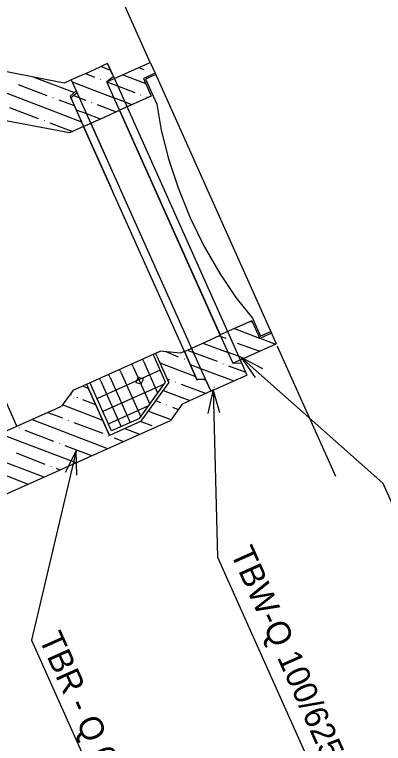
# Model space of a CAD drawing. Extents: x -781656 to -760591, y -1008106 to -975620.
# Drawn here: x -781651.298 to -781650.365, y -1008099.231 to -1008097.386 of the extents above; entities that cross this region are included whole.
import ezdxf

# ---------------------------------------------------------------- set-up
doc = ezdxf.new("R2010")
doc.units = 0
doc.layers.add('Implicitní', color=7, linetype='Continuous')

msp = doc.modelspace()

# ---------------------------------------------------------------- linework, layer by layer
at = {"layer": 'Implicitní'}
for points in [[(-781650.9548, -1008097.5069), (-781651.1925, -1008096.9755)], [(-781651.1726, -1008097.5591), (-781651.8094, -1008097.4335)], [(-781651.0628, -1008097.51), (-781651.0815, -1008097.5183)], [(-781651.0787, -1008097.5171), (-781651.0555, -1008097.5263)], [(-781651.0646, -1008097.5561), (-781650.9548, -1008097.5069)], [(-781651.0628, -1008097.51), (-781651.0503, -1008097.5378), (-781651.0628, -1008097.51)], [(-781650.9548, -1008097.5069), (-781650.9424, -1008097.5345)], [(-781651.4547, -1008097.5323), (-781651.1286, -1008097.6573)], [(-781651.1182, -1008097.5348), (-781651.1546, -1008097.551), (-781651.1421, -1008097.5789)], [(-781651.1189, -1008097.5351), (-781651.0956, -1008097.5442)], [(-781651.1182, -1008097.5348), (-781651.0815, -1008097.5183)], [(-781650.9843, -1008097.5202), (-781650.9712, -1008097.5249)], [(-781650.9424, -1008097.5345), (-781650.972, -1008097.5477), (-781650.9521, -1008097.5923)], [(-781650.9569, -1008097.5304), (-781650.9566, -1008097.531)], [(-781650.9424, -1008097.5345), (-781650.648, -1008098.1927)], [(-781651.2498, -1008097.5443), (-781651.1468, -1008097.583)], [(-781651.1546, -1008097.551), (-781651.1726, -1008097.5591)], [(-781651.1546, -1008097.551), (-781651.1421, -1008097.5789)], [(-781651.0815, -1008097.5493), (-781651.081, -1008097.5504)], [(-781651.048, -1008097.5429), (-781651.0646, -1008097.5561)], [(-781651.0503, -1008097.5378), (-781651.048, -1008097.5429)], [(-781651.048, -1008097.5429), (-781650.7231, -1008098.2692)], [(-781651.0245, -1008097.5381), (-781650.9664, -1008097.5603)], [(-781650.9409, -1008097.5379), (-781650.9668, -1008097.5494), (-781650.9383, -1008097.613)], [(-781651.1591, -1008097.6849), (-781651.8058, -1008097.5637)], [(-781651.2888, -1008097.5629), (-781651.2164, -1008097.5905)], [(-781651.1521, -1008097.5565), (-781651.0466, -1008097.5962)], [(-781651.066, -1008097.5555), (-781651.0646, -1008097.5561)], [(-781651.0323, -1008097.6281), (-781651.0646, -1008097.5561)], [(-781651.0646, -1008097.5561), (-781651.0375, -1008097.5664)], [(-781651.0375, -1008097.5664), (-781650.9937, -1008097.5831)], [(-781651.1421, -1008097.5789), (-781651.1578, -1008097.5921)], [(-781651.1398, -1008097.584), (-781651.1557, -1008097.5968)], [(-781651.1484, -1008097.5911), (-781651.1342, -1008097.5966), (-781651.1177, -1008097.6023)], [(-781651.1421, -1008097.5789), (-781650.8166, -1008098.3065)], [(-781651.1421, -1008097.5789), (-781651.1398, -1008097.584)], [(-781650.9794, -1008097.5886), (-781650.979, -1008097.5896)], [(-781651.2011, -1008097.5955), (-781651.2007, -1008097.5966)], [(-781651.1864, -1008097.602), (-781651.147, -1008097.6162)], [(-781651.1578, -1008097.5921), (-781651.1234, -1008097.6689)], [(-781651.1557, -1008097.5968), (-781651.1234, -1008097.6689)], [(-781651.1313, -1008097.603), (-781651.131, -1008097.6037)], [(-781651.1032, -1008097.6084), (-781651.1027, -1008097.6094)], [(-781651.001, -1008097.6142), (-781651.0196, -1008097.6065), (-781651.0466, -1008097.5962)], [(-781650.9521, -1008097.5923), (-781651.0323, -1008097.6281)], [(-781650.9638, -1008097.5943), (-781650.9609, -1008097.5962)], [(-781651.3109, -1008097.621), (-781651.2386, -1008097.6486)], [(-781651.1422, -1008097.6271), (-781651.1162, -1008097.6367), (-781651.0813, -1008097.6501)], [(-781651.0889, -1008097.6139), (-781651.0412, -1008097.6321)], [(-781651.069, -1008097.6446), (-781651.0323, -1008097.6281)], [(-781651.0323, -1008097.6281), (-781650.7779, -1008098.197)], [(-781650.7774, -1008098.198), (-781651.0323, -1008097.6281)], [(-781650.9383, -1008097.613), (-781650.9273, -1008097.6787), (-781650.9089, -1008097.7508), (-781650.8844, -1008097.8247), (-781650.854, -1008097.9001), (-781650.8181, -1008097.973), (-781650.779, -1008098.0412), (-781650.7379, -1008098.102), (-781650.6962, -1008098.1543)], [(-781651.1234, -1008097.6689), (-781651.069, -1008097.6446)], [(-781651.2233, -1008097.6536), (-781651.2229, -1008097.6546)], [(-781651.2086, -1008097.6601), (-781651.152, -1008097.6817)], [(-781651.1054, -1008097.6608), (-781651.0374, -1008097.8128)], [(-781651.1054, -1008097.6608), (-781651.105, -1008097.6619)], [(-781651.1234, -1008097.6689), (-781651.1591, -1008097.6849)], [(-781650.8685, -1008098.2387), (-781651.1234, -1008097.6689)], [(-781651.1234, -1008097.6689), (-781651.0555, -1008097.8209)], [(-781651.1234, -1008097.6689), (-781651.123, -1008097.6699)], [(-781650.6976, -1008098.1611), (-781650.7779, -1008098.197)], [(-781650.701, -1008098.1626), (-781650.696, -1008098.1648)], [(-781650.6976, -1008098.1611), (-781650.6776, -1008098.2059)], [(-781650.6962, -1008098.1543), (-781650.6758, -1008098.1999), (-781650.65, -1008098.1883)], [(-781650.7412, -1008098.1805), (-781650.678, -1008098.2049)], [(-781650.8141, -1008098.2144), (-781650.7774, -1008098.198)], [(-781650.7801, -1008098.1992), (-781650.7762, -1008098.2007)], [(-781650.7774, -1008098.198), (-781650.7458, -1008098.2687)], [(-781650.7762, -1008098.2007), (-781650.7634, -1008098.2056)], [(-781650.648, -1008098.1927), (-781650.6776, -1008098.2059)], [(-781650.648, -1008098.1927), (-781650.636, -1008098.2196)], [(-781650.8685, -1008098.2387), (-781650.8141, -1008098.2144)], [(-781650.8213, -1008098.2176), (-781650.7578, -1008098.2418)], [(-781650.7491, -1008098.211), (-781650.7487, -1008098.2121)], [(-781650.7344, -1008098.2175), (-781650.6778, -1008098.2383)], [(-781650.6765, -1008098.2055), (-781650.6377, -1008098.2203)], [(-781650.8589, -1008098.2365), (-781650.8457, -1008098.2416), (-781650.7856, -1008098.2637)], [(-781650.7458, -1008098.2687), (-781650.636, -1008098.2196)], [(-781650.6332, -1008098.2257), (-781650.4862, -1008098.5545)], [(-781650.6332, -1008098.2257), (-781650.6328, -1008098.2267)], [(-781651.1502, -1008098.337), (-781650.9299, -1008098.2384)], [(-781650.9444, -1008098.2535), (-781650.9476, -1008098.2463)], [(-781650.9161, -1008098.3167), (-781650.9444, -1008098.2535)], [(-781650.9383, -1008098.2507), (-781650.9414, -1008098.2436)], [(-781650.9383, -1008098.2507), (-781650.908, -1008098.3184)], [(-781650.8685, -1008098.2387), (-781650.8791, -1008098.2435), (-781650.9299, -1008098.2384)], [(-781650.9152, -1008098.2392), (-781650.8838, -1008098.2521)], [(-781650.8369, -1008098.3095), (-781650.8685, -1008098.2387)], [(-781650.8685, -1008098.2387), (-781650.8366, -1008098.3101)], [(-781650.7183, -1008098.2564), (-781650.7312, -1008098.2512), (-781650.7578, -1008098.2418)], [(-781650.7245, -1008098.254), (-781650.3662, -1008098.5724), (-781649.9068, -1008099.5994)], [(-781650.6698, -1008098.2832), (-781650.7245, -1008098.254), (-781650.6895, -1008098.3052)], [(-781650.9981, -1008098.2775), (-781651.0013, -1008098.2704)], [(-781650.9712, -1008098.2655), (-781650.9744, -1008098.2584)], [(-781650.9712, -1008098.2655), (-781650.9361, -1008098.344)], [(-781650.9306, -1008098.2677), (-781650.8401, -1008098.3023)], [(-781650.8688, -1008098.2572), (-781650.8685, -1008098.2579)], [(-781650.8538, -1008098.2717), (-781650.8277, -1008098.2817), (-781650.7429, -1008098.3135)], [(-781650.7709, -1008098.2701), (-781650.7704, -1008098.2711)], [(-781650.7231, -1008098.2692), (-781650.7458, -1008098.2687)], [(-781650.7458, -1008098.2687), (-781650.7455, -1008098.2694)], [(-781650.7231, -1008098.2692), (-781650.7099, -1008098.2988)], [(-781650.9296, -1008098.2865), (-781651.0887, -1008098.3576)], [(-781651.0294, -1008098.2915), (-781651.0326, -1008098.2844)], [(-781651.0294, -1008098.2915), (-781650.979, -1008098.404)], [(-781650.9981, -1008098.2775), (-781650.9558, -1008098.372)], [(-781650.7566, -1008098.2756), (-781650.7131, -1008098.2916)], [(-781651.08, -1008098.3142), (-781651.0832, -1008098.307)], [(-781651.0566, -1008098.3045), (-781651.0601, -1008098.2967)], [(-781651.0566, -1008098.3045), (-781651.0054, -1008098.4191)], [(-781650.9851, -1008098.3039), (-781650.991, -1008098.3172)], [(-781650.9775, -1008098.3209), (-781650.9723, -1008098.3088), (-781650.9851, -1008098.3039)], [(-781650.9127, -1008098.3079), (-781650.9063, -1008098.3103)], [(-781650.8149, -1008098.3102), (-781650.8369, -1008098.3095)], [(-781650.8369, -1008098.3095), (-781650.8366, -1008098.3101)], [(-781650.8366, -1008098.3101), (-781650.8361, -1008098.3112)], [(-781650.8184, -1008098.3098), (-781650.8142, -1008098.3119)], [(-781650.8166, -1008098.3065), (-781650.8017, -1008098.3398)], [(-781650.8149, -1008098.3102), (-781650.8017, -1008098.3398)], [(-781650.7466, -1008098.3152), (-781650.7099, -1008098.2988)], [(-781651.3436, -1008098.3142), (-781651.293, -1008098.4274)], [(-781651.1261, -1008098.3262), (-781651.1115, -1008098.3323)], [(-781651.1162, -1008098.3218), (-781651.0583, -1008098.4513)], [(-781651.0583, -1008098.4513), (-781651.113, -1008098.3289)], [(-781651.1042, -1008098.325), (-781651.1074, -1008098.3178)], [(-781651.0526, -1008098.4402), (-781651.1042, -1008098.325)], [(-781651.08, -1008098.3142), (-781651.0285, -1008098.4294)], [(-781650.9193, -1008098.3214), (-781651.0747, -1008098.3909)], [(-781650.991, -1008098.3172), (-781650.9775, -1008098.3209)], [(-781650.9822, -1008098.4087), (-781650.9161, -1008098.3167)], [(-781650.978, -1008098.4154), (-781650.908, -1008098.3184)], [(-781650.892, -1008098.3158), (-781650.8916, -1008098.3168)], [(-781650.8764, -1008098.3214), (-781650.8136, -1008098.3451)], [(-781650.8098, -1008098.3218), (-781650.8076, -1008098.3221)], [(-781650.8017, -1008098.3398), (-781650.7466, -1008098.3152)], [(-781650.793, -1008098.3282), (-781650.7926, -1008098.3292)], [(-781651.1502, -1008098.337), (-781651.1793, -1008098.3778)], [(-781651.1573, -1008098.3475), (-781651.1549, -1008098.3485)], [(-781650.9218, -1008098.3377), (-781650.8544, -1008098.3634)], [(-781650.8017, -1008098.3398), (-781650.8741, -1008098.3722)], [(-781650.7788, -1008098.3944), (-781650.7955, -1008098.3351), (-781650.8089, -1008098.3958)], [(-781650.7955, -1008098.3351), (-781650.7843, -1008098.7594), (-781650.4711, -1008099.4596)], [(-781651.1401, -1008098.3549), (-781651.1397, -1008098.3559)], [(-781651.1259, -1008098.3604), (-781651.0934, -1008098.3728)], [(-781650.9398, -1008098.3641), (-781650.9285, -1008098.3684)], [(-781651.2062, -1008098.3898), (-781651.1793, -1008098.3778)], [(-781651.1763, -1008098.3744), (-781651.0754, -1008098.4129)], [(-781650.959, -1008098.3767), (-781651.06, -1008098.4219)], [(-781650.9142, -1008098.3738), (-781650.9137, -1008098.3748)], [(-781650.8741, -1008098.3722), (-781650.9039, -1008098.4133)], [(-781650.8985, -1008098.3798), (-781650.8839, -1008098.386)], [(-781651.2062, -1008098.3898), (-781651.3979, -1008098.4755)], [(-781651.214, -1008098.3933), (-781651.1769, -1008098.4069)], [(-781650.9596, -1008098.39), (-781650.9027, -1008098.4115)], [(-781651.4023, -1008098.6362), (-781650.9039, -1008098.4133)], [(-781651.2541, -1008098.4112), (-781651.063, -1008098.4845)], [(-781651.1623, -1008098.413), (-781651.1619, -1008098.414)], [(-781651.148, -1008098.4184), (-781651.075, -1008098.4458)], [(-781650.978, -1008098.4154), (-781651.0583, -1008098.4513)], [(-781650.9822, -1008098.4087), (-781651.0526, -1008098.4402)], [(-781650.979, -1008098.4159), (-781650.9506, -1008098.4264)], [(-781651.2867, -1008098.4323), (-781651.2864, -1008098.433)], [(-781651.2724, -1008098.4378), (-781651.1998, -1008098.4661)], [(-781651.0192, -1008098.4338), (-781650.9824, -1008098.4484)], [(-781651.3347, -1008098.4473), (-781651.1433, -1008098.5204)], [(-781651.0603, -1008098.4522), (-781651.06, -1008098.4529)], [(-781651.046, -1008098.4577), (-781651.0229, -1008098.4665)], [(-781651.1845, -1008098.4711), (-781651.184, -1008098.4721)], [(-781651.1706, -1008098.4767), (-781651.1031, -1008098.5024)], [(-781651.3899, -1008098.4936), (-781651.2245, -1008098.5567)], [(-781651.2946, -1008098.4958), (-781651.2218, -1008098.5245)], [(-781651.1424, -1008098.4902), (-781651.2553, -1008098.9701), (-781650.7857, -1008100.0199)], [(-781651.141, -1008098.5521), (-781651.1424, -1008098.4902), (-781651.1703, -1008098.5454)], [(-781651.2068, -1008098.5296), (-781651.2065, -1008098.5303)], [(-781651.1927, -1008098.5347), (-781651.1834, -1008098.5383)], [(-781651.3168, -1008098.5539), (-781651.2646, -1008098.5746)]]:
    msp.add_lwpolyline(points, dxfattribs=at)

# ---------------------------------------------------------------- texts
for s, height, p in [('VZOROVÁ ŠACHTA S KONUSEM DLE ČSN EN 1917', 0.12627, (-781650.6076, -1008096.2958)), ('TBW-Q 100/625/120', 0.06, (-781650.7529, -1008098.7487)), ('TBR - Q 600/1000x625/120 SPK', 0.06, (-781651.2376, -1008098.9655)), ('TBS - Q - 250/1000/120 - SP', 0.06, (-781651.5434, -1008099.1023))]:
    msp.add_text(s, height=height, rotation=294.1003, dxfattribs=at).set_placement(p)

doc.saveas('drawing.dxf')
